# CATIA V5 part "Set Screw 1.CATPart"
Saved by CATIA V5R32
Part number: Set Screw-13
Bounding box of the stored display mesh (mm): x -5.367 to 5.367, y -5.448 to 5.448, z -1.732 to 16
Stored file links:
  D:\PROJECTS\Project 2022\CATIA V5 6R 2022\Resources\Tutorial Files\c13_catia_v5_6r2022_tut\c13tut2\Bench vice\Set Screw 1.CATPart
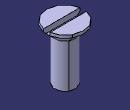
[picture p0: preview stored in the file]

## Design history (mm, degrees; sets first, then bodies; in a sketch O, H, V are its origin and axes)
Body1 (main body)
  Sketch1 on yz-plane, origin (0, 0, 0), H (0, 1, 0), V (0, 0, 1)
    point P1 (0, -1.7321)
    line L1 (0, -1.7321) -> (3, 0)
    point P2 (3, 0)
    line L2 (3, 0) -> (3, 12.7)
    point P3 (0, 16)
    line L3 (0, 16) -> (0, -1.7321)
    line L4 (0, 16) -> (5.45, 16)
    line L5 (5.45, 16) -> (5.45, 15.15)
    line L6 (5.45, 15.15) -> (3, 12.7)
    point P6 (3, 12.7)
    distance L2 L3 = 3
    distance L4 P6 = 3.3
    distance L5 L3 = 5.45
    angle L6 L3 = 45
    distance L4 P2 = 16
    angle L1 L3 = 60
    coincidence: P1 V, P2 H, P3 V
    vertical: L2 V, L3 V, L5 V
    horizontal: L4 H
  Shaft1: profile Sketch1, axis edge of Sketch1, angle 360
  Sketch2 on yz-plane, origin (0, 0, 0), H (0, 1, 0), V (0, 0, 1)
    line L1 (-0.95, 18.4475) -> (0.95, 18.4475)
    line L2 (0.95, 18.4475) -> (0.95, 14.4)
    line L3 (0.95, 14.4) -> (-0.95, 14.4)
    line L4 (-0.95, 14.4) -> (-0.95, 18.4475)
    reference projected line E1 (5.45, 16) -> (-5.45, 16) from edge [face of Shaft1 from Sketch1.L4 | face of Shaft1 from Sketch1.L5]
    distance L4 L2 = 1.9
    distance E1 L3 = 1.6
    horizontal: L1 H, L3 H
    vertical: L2 V, L4 V
    symmetry: L2 L4 V
  Pocket1: profile Sketch2, direction (-1, 0, 0), length 16, mirrored extent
